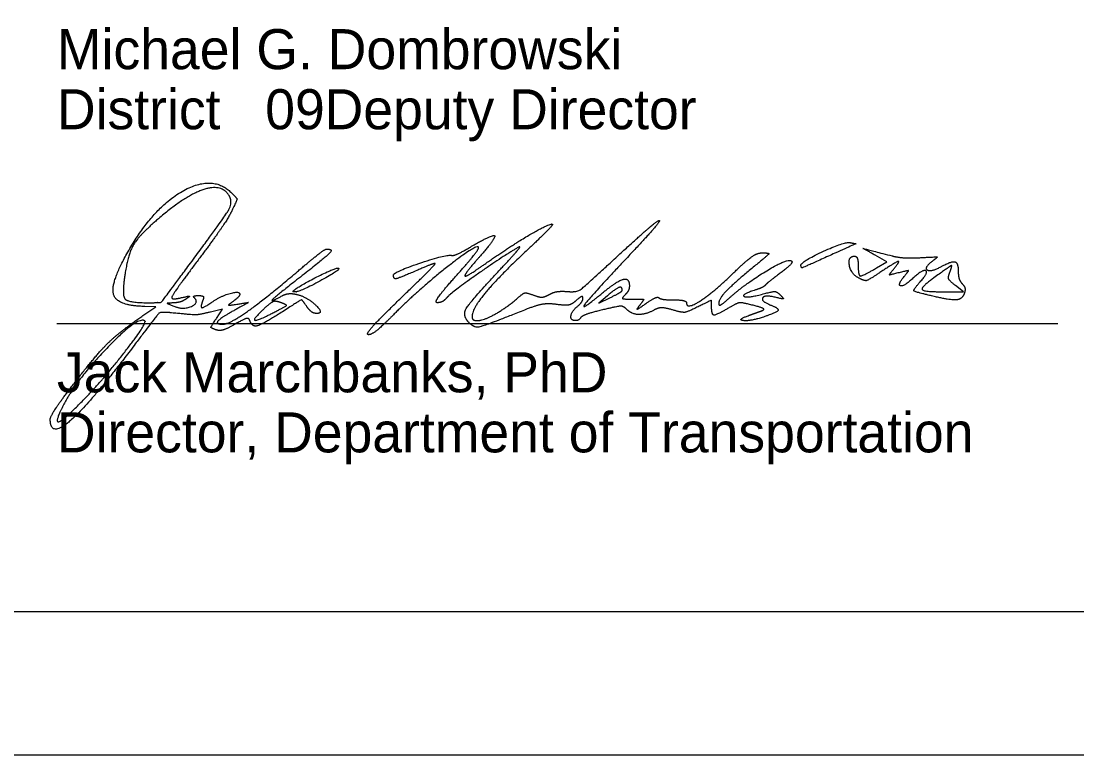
# Model space of a CAD drawing. Extents: x 0 to 34, y 0 to 22.
# Drawn here: x 27.362 to 31.053, y 0 to 2.565 of the extents above; entities that cross this region are included whole.
import ezdxf

# ---------------------------------------------------------------- set-up
doc = ezdxf.new("R2010")
doc.units = 0
for name, color, linetype in [('SH_Border', 7, 'Continuous'), ('SH_Cut_Line', 7, 'Continuous'), ('SH_Data', 7, 'Continuous'), ('SH_Text', 7, 'Continuous')]:
    doc.layers.add(name, color=color, linetype=linetype)

msp = doc.modelspace()

# ---------------------------------------------------------------- linework, layer by layer
at = {"layer": 'SH_Border'}
msp.add_lwpolyline([(1.5, 21.5), (33.5, 21.5), (33.5, 0.5), (1.5, 0.5)], close=True, dxfattribs=at)
at = {"layer": 'SH_Cut_Line'}
msp.add_lwpolyline([(0, 0), (34, 0), (34, 22), (0, 22)], close=True, dxfattribs=at)
at = {"layer": 'SH_Data'}
msp.add_line((27.4871, 1.5073), (30.9871, 1.5073), dxfattribs=at)
at = {"layer": 'SH_Text'}
for p, q in [((27.9494, 1.7123), (27.9494, 1.7123)), ((30.0887, 1.7115), (30.0887, 1.7115)), ((29.4637, 1.6245), (29.4637, 1.6245)), ((28.3147, 1.6225), (28.3147, 1.6225)), ((28.6865, 1.5934), (28.6865, 1.5934)), ((30.5412, 1.6052), (30.5412, 1.6052)), ((28.2699, 1.5808), (28.2699, 1.5808))]:
    msp.add_line(p, q, dxfattribs=at)
for points in [[(30.3525, 1.7019), (30.3889, 1.7234), (30.3481, 1.7464)], [(30.6012, 1.6184), (30.6574, 1.6185), (30.6287, 1.6406)], [(29.4119, 1.6048), (29.3824, 1.5792), (29.423, 1.5989)], [(27.8017, 1.5454), (27.8324, 1.5666), (27.7946, 1.5673)], [(28.0447, 1.5255), (28.0659, 1.5579), (28.0241, 1.5478)]]:
    msp.add_lwpolyline(points, dxfattribs=at)
for points in [[(27.7381, 1.7631), (27.8243, 1.9135), (28.0324, 2.0295), (28.0981, 1.9638)], [(28.0891, 1.9546), (28.0632, 1.9967), (27.9371, 1.9555), (27.8417, 1.8739)], [(28.0981, 1.9638), (28.1169, 1.9451), (28.1169, 1.94), (28.0986, 1.9016)], [(27.9494, 1.7123), (28.0707, 1.8758), (28.1032, 1.932), (28.0891, 1.9546)], [(28.0986, 1.9016), (28.0876, 1.8786), (28.0359, 1.803), (27.9837, 1.7337)], [(27.8417, 1.8739), (27.7751, 1.8168), (27.7363, 1.7527), (27.7252, 1.6815)], [(28.9918, 1.7216), (29.0723, 1.7782), (29.2037, 1.8554), (29.2194, 1.8554)], [(29.2194, 1.8554), (29.2242, 1.8554), (29.1829, 1.8128), (29.1276, 1.7607)], [(29.4461, 1.742), (29.5211, 1.8111), (29.5871, 1.8677), (29.5928, 1.8678)], [(29.5928, 1.8678), (29.5986, 1.8678), (29.5465, 1.8077), (29.4772, 1.7341)], [(28.9328, 1.7751), (29.0116, 1.8212), (29.0238, 1.808), (28.9646, 1.7407)], [(28.9609, 1.7748), (28.9513, 1.7844), (28.7416, 1.6175), (28.6637, 1.5382)], [(29.1012, 1.7744), (29.0521, 1.7466), (28.8638, 1.6144), (28.8506, 1.5984)], [(28.8672, 1.7458), (28.8728, 1.744), (28.9023, 1.7572), (28.9328, 1.7751)], [(28.8831, 1.6744), (28.9294, 1.7262), (28.9644, 1.7713), (28.9609, 1.7748)], [(29.036, 1.6954), (29.0821, 1.7447), (29.1115, 1.7802), (29.1012, 1.7744)], [(30.0887, 1.7115), (30.0887, 1.7239), (30.2415, 1.7942), (30.2604, 1.7905)], [(30.2604, 1.7905), (30.2811, 1.7865), (30.2818, 1.7869), (30.1602, 1.7322)], [(27.7946, 1.5673), (27.6967, 1.5689), (27.6732, 1.6501), (27.7381, 1.7631)], [(28.3282, 1.6896), (28.3786, 1.7325), (28.4241, 1.7676), (28.4293, 1.7677)], [(28.4293, 1.7677), (28.4542, 1.7682), (28.4308, 1.7427), (28.3449, 1.6754)], [(28.6639, 1.6773), (28.6641, 1.6878), (28.8515, 1.751), (28.8672, 1.7458)], [(28.9646, 1.7407), (28.9366, 1.7089), (28.9137, 1.6792), (28.9137, 1.6747)], [(29.1276, 1.7607), (29.0279, 1.667), (28.9387, 1.5588), (28.9387, 1.5319)], [(29.2711, 1.6196), (29.3045, 1.6168), (29.328, 1.6332), (29.4461, 1.742)], [(29.8543, 1.6857), (29.8995, 1.7295), (29.9366, 1.7552), (29.9543, 1.7548)], [(29.9543, 1.7548), (29.9786, 1.7544), (29.9748, 1.748), (29.9262, 1.708)], [(30.2897, 1.6674), (30.2632, 1.6815), (30.2522, 1.7429), (30.2762, 1.7429)], [(30.2762, 1.7429), (30.283, 1.7429), (30.2887, 1.7288), (30.2887, 1.7117)], [(30.3481, 1.7464), (30.3053, 1.7705), (30.3044, 1.7705), (30.4074, 1.7441)], [(30.4074, 1.7441), (30.428, 1.7388), (30.473, 1.7361), (30.5074, 1.738)], [(30.5074, 1.738), (30.5623, 1.7411), (30.5672, 1.7395), (30.5473, 1.7247)], [(27.8032, 1.5804), (27.8499, 1.5804), (27.8545, 1.5845), (27.9494, 1.7123)], [(27.9837, 1.7337), (27.9314, 1.6643), (27.8887, 1.6037), (27.8887, 1.5989)], [(28.3147, 1.6225), (28.3351, 1.6403), (28.4671, 1.7061), (28.4723, 1.701)], [(28.4723, 1.701), (28.4785, 1.6948), (28.3359, 1.6179), (28.3182, 1.6179)], [(28.6865, 1.5934), (28.7575, 1.6619), (28.8129, 1.7179), (28.8094, 1.7179)], [(28.8094, 1.7179), (28.806, 1.7179), (28.777, 1.7067), (28.7449, 1.6929)], [(28.9137, 1.6747), (28.9137, 1.6703), (28.9488, 1.6914), (28.9918, 1.7216)], [(29.4772, 1.7341), (29.3477, 1.5965), (29.3156, 1.5493), (29.3978, 1.617)], [(29.9262, 1.708), (29.8521, 1.647), (29.8012, 1.5935), (29.8012, 1.5767)], [(29.8355, 1.5945), (29.8892, 1.6433), (30.0361, 1.7333), (30.053, 1.7277)], [(30.053, 1.7277), (30.0614, 1.7249), (30.0462, 1.7062), (30.0191, 1.686)], [(30.1602, 1.7322), (30.0977, 1.7041), (30.0887, 1.7015), (30.0887, 1.7115)], [(30.2887, 1.7117), (30.2887, 1.6748), (30.3029, 1.6727), (30.3525, 1.7019)], [(30.4121, 1.6971), (30.4365, 1.7267), (30.4207, 1.7229), (30.3644, 1.6857)], [(30.5473, 1.7247), (30.5185, 1.7032), (30.5414, 1.6868), (30.5751, 1.7048)], [(30.6089, 1.6861), (30.6188, 1.7119), (30.6106, 1.7088), (30.548, 1.6632)], [(30.5751, 1.7048), (30.6153, 1.7264), (30.6387, 1.7206), (30.6387, 1.6892)], [(27.7252, 1.6815), (27.7137, 1.6081), (27.7352, 1.5804), (27.8032, 1.5804)], [(28.0668, 1.5054), (28.0899, 1.5054), (28.2159, 1.5942), (28.3282, 1.6896)], [(28.3449, 1.6754), (28.2517, 1.6024), (28.2302, 1.5808), (28.2741, 1.6043)], [(28.7449, 1.6929), (28.6823, 1.6661), (28.6636, 1.6625), (28.6639, 1.6773)], [(28.8173, 1.5804), (28.807, 1.5804), (28.8359, 1.6217), (28.8831, 1.6744)], [(28.9289, 1.5098), (28.9037, 1.535), (28.9326, 1.5851), (29.036, 1.6954)], [(29.3978, 1.617), (29.4462, 1.6569), (29.4887, 1.6673), (29.4887, 1.6392)], [(29.6887, 1.5789), (29.6887, 1.5561), (29.784, 1.6175), (29.8543, 1.6857)], [(30.0191, 1.686), (29.992, 1.6658), (29.9671, 1.6458), (29.9637, 1.6415)], [(30.3644, 1.6857), (30.3244, 1.6592), (30.3111, 1.6559), (30.2897, 1.6674)], [(30.4315, 1.6854), (30.3984, 1.6771), (30.3966, 1.6782), (30.4121, 1.6971)], [(30.4516, 1.6746), (30.4662, 1.6922), (30.4639, 1.6934), (30.4315, 1.6854)], [(30.4803, 1.6659), (30.4484, 1.6359), (30.4253, 1.643), (30.4516, 1.6746)], [(30.5054, 1.6532), (30.5359, 1.6869), (30.5143, 1.6978), (30.4803, 1.6659)], [(30.548, 1.6632), (30.5053, 1.6321), (30.5218, 1.6183), (30.6012, 1.6184)], [(30.6287, 1.6406), (30.6083, 1.6563), (30.6026, 1.6695), (30.6089, 1.6861)], [(30.6387, 1.6892), (30.6387, 1.6733), (30.645, 1.654), (30.6528, 1.6462)], [(29.4637, 1.6245), (29.4637, 1.638), (29.4396, 1.6288), (29.4119, 1.6048)], [(29.423, 1.5989), (29.4454, 1.6097), (29.4637, 1.6212), (29.4637, 1.6245)], [(29.4887, 1.6392), (29.4887, 1.6302), (29.4819, 1.6162), (29.4737, 1.6079)], [(29.9293, 1.625), (29.8798, 1.6095), (29.8993, 1.5959), (29.9511, 1.6097)], [(29.9637, 1.6415), (29.9602, 1.6373), (29.9448, 1.6298), (29.9293, 1.625)], [(30.5412, 1.6052), (30.4864, 1.6182), (30.4807, 1.6259), (30.5054, 1.6532)], [(30.6528, 1.6462), (30.6606, 1.6385), (30.6636, 1.6233), (30.6595, 1.6125)], [(27.8887, 1.5989), (27.8887, 1.5941), (27.9041, 1.5938), (27.923, 1.5982)], [(27.9387, 1.5935), (27.9284, 1.5865), (27.9087, 1.5803), (27.8949, 1.5798)], [(27.8991, 1.5671), (27.929, 1.5552), (27.9852, 1.5797), (27.9678, 1.5972)], [(27.923, 1.5982), (27.9485, 1.6041), (27.9526, 1.6029), (27.9387, 1.5935)], [(27.9678, 1.5972), (27.9632, 1.6017), (27.9695, 1.6054), (27.9817, 1.6054)], [(27.9817, 1.6054), (27.9962, 1.6054), (28.0014, 1.599), (27.9966, 1.5867)], [(28.0328, 1.5848), (28.0617, 1.6046), (28.1262, 1.6221), (28.1262, 1.6101)], [(28.1262, 1.6101), (28.1262, 1.6056), (28.1164, 1.5948), (28.1045, 1.5861)], [(28.2741, 1.6043), (28.2868, 1.6111), (28.3107, 1.6132), (28.3273, 1.609)], [(28.3603, 1.5676), (28.3434, 1.5916), (28.3414, 1.5912), (28.2756, 1.5488)], [(28.3182, 1.6179), (28.3134, 1.6179), (28.3118, 1.62), (28.3147, 1.6225)], [(28.3273, 1.609), (28.3634, 1.5998), (28.4217, 1.5429), (28.395, 1.5429)], [(28.5762, 1.4686), (28.5659, 1.4688), (28.6155, 1.525), (28.6865, 1.5934)], [(28.8506, 1.5984), (28.8423, 1.5885), (28.8274, 1.5804), (28.8173, 1.5804)], [(28.9567, 1.5179), (28.9784, 1.5179), (29.0598, 1.5631), (29.0962, 1.5954)], [(29.0962, 1.5954), (29.1165, 1.6134), (29.1293, 1.6161), (29.1531, 1.6071)], [(29.1531, 1.6071), (29.1733, 1.5994), (29.1921, 1.6001), (29.2081, 1.6091)], [(29.2081, 1.6091), (29.2215, 1.6167), (29.2498, 1.6214), (29.2711, 1.6196)], [(29.3036, 1.5889), (29.2879, 1.5747), (29.2667, 1.5703), (29.2341, 1.5744)], [(29.3262, 1.5964), (29.3262, 1.6035), (29.316, 1.6001), (29.3036, 1.5889)], [(29.3074, 1.5679), (29.3177, 1.5765), (29.3262, 1.5893), (29.3262, 1.5964)], [(29.4737, 1.6079), (29.462, 1.5962), (29.4679, 1.5929), (29.5002, 1.5929)], [(29.5002, 1.5929), (29.5377, 1.5929), (29.5401, 1.5909), (29.5246, 1.5715)], [(29.5463, 1.5774), (29.5677, 1.5924), (29.5885, 1.6015), (29.5924, 1.5975)], [(29.5924, 1.5975), (29.5963, 1.5936), (29.6196, 1.5904), (29.6441, 1.5904)], [(29.6441, 1.5904), (29.6686, 1.5904), (29.6887, 1.5852), (29.6887, 1.5789)], [(29.7762, 1.5663), (29.7762, 1.5892), (29.7751, 1.5892), (29.729, 1.5664)], [(29.8012, 1.5767), (29.8012, 1.5693), (29.8166, 1.5773), (29.8355, 1.5945)], [(29.9511, 1.6097), (29.9894, 1.6199), (30.0047, 1.6193), (30.0167, 1.6071)], [(29.998, 1.5996), (29.9613, 1.6087), (29.9481, 1.5856), (29.9824, 1.5724)], [(30.0167, 1.6071), (30.0294, 1.5942), (30.0258, 1.5928), (29.998, 1.5996)], [(30.6595, 1.6125), (30.6514, 1.5914), (30.6102, 1.5889), (30.5412, 1.6052)], [(27.8949, 1.5798), (27.8725, 1.5789), (27.8729, 1.5776), (27.8991, 1.5671)], [(27.9966, 1.5867), (27.9877, 1.5634), (28.0006, 1.5627), (28.0328, 1.5848)], [(28.1114, 1.5561), (28.0603, 1.5279), (28.0405, 1.5054), (28.0668, 1.5054)], [(28.1045, 1.5861), (28.0856, 1.5723), (28.0876, 1.571), (28.1202, 1.5759)], [(28.1202, 1.5759), (28.1569, 1.5815), (28.1568, 1.5812), (28.1114, 1.5561)], [(28.2168, 1.5643), (28.1725, 1.5238), (28.1838, 1.5149), (28.2418, 1.5445)], [(28.2699, 1.5808), (28.2527, 1.5872), (28.2362, 1.582), (28.2168, 1.5643)], [(28.2418, 1.5445), (28.2882, 1.5682), (28.2917, 1.5728), (28.2699, 1.5808)], [(28.395, 1.5429), (28.3854, 1.5429), (28.3698, 1.554), (28.3603, 1.5676)], [(29.1285, 1.5573), (28.9825, 1.4996), (28.9474, 1.4913), (28.9289, 1.5098)], [(29.2341, 1.5744), (29.2049, 1.5782), (29.165, 1.5717), (29.1285, 1.5573)], [(29.3004, 1.5179), (29.2821, 1.5179), (29.2866, 1.5507), (29.3074, 1.5679)], [(29.3947, 1.5554), (29.3564, 1.5462), (29.3221, 1.534), (29.3186, 1.5283)], [(29.4791, 1.5575), (29.468, 1.5686), (29.4479, 1.5681), (29.3947, 1.5554)], [(29.5754, 1.555), (29.5446, 1.5385), (29.4968, 1.5398), (29.4791, 1.5575)], [(29.5246, 1.5715), (29.5125, 1.5565), (29.519, 1.5583), (29.5463, 1.5774)], [(29.6399, 1.5551), (29.613, 1.5628), (29.5899, 1.5627), (29.5754, 1.555)], [(29.729, 1.5664), (29.6916, 1.5479), (29.673, 1.5456), (29.6399, 1.5551)], [(29.8381, 1.5633), (29.7931, 1.5367), (29.7762, 1.5375), (29.7762, 1.5663)], [(29.9213, 1.5713), (29.8825, 1.5812), (29.8657, 1.5796), (29.8381, 1.5633)], [(29.9074, 1.5364), (29.9212, 1.5413), (29.9409, 1.5484), (29.9512, 1.5521)], [(29.9512, 1.5521), (29.9626, 1.5563), (29.9509, 1.5638), (29.9213, 1.5713)], [(29.9824, 1.5724), (30.013, 1.5607), (30.004, 1.5458), (29.9573, 1.5304)], [(27.7946, 1.5161), (27.7737, 1.5371), (27.5552, 1.3114), (27.5089, 1.221)], [(27.5508, 1.3032), (27.6284, 1.4036), (27.7085, 1.4809), (27.8017, 1.5454)], [(27.579, 1.2398), (27.6466, 1.3088), (27.8023, 1.5085), (27.7946, 1.5161)], [(27.8829, 1.5455), (27.8495, 1.5488), (27.8378, 1.5383), (27.7611, 1.4367)], [(28.0241, 1.5478), (27.9838, 1.538), (27.9615, 1.5377), (27.8829, 1.5455)], [(28.0435, 1.4855), (28.0253, 1.4925), (28.0254, 1.4961), (28.0447, 1.5255)], [(28.1612, 1.5191), (28.1583, 1.5276), (28.1391, 1.5225), (28.11, 1.5053)], [(28.2756, 1.5488), (28.2068, 1.5045), (28.1693, 1.4947), (28.1612, 1.5191)], [(28.6637, 1.5382), (28.6259, 1.4997), (28.5865, 1.4684), (28.5762, 1.4686)], [(28.9387, 1.5319), (28.9387, 1.5242), (28.9468, 1.5179), (28.9567, 1.5179)], [(29.3186, 1.5283), (29.3151, 1.5226), (29.3069, 1.5179), (29.3004, 1.5179)], [(29.9573, 1.5304), (29.9107, 1.515), (29.8634, 1.5207), (29.9074, 1.5364)], [(28.11, 1.5053), (28.0844, 1.4902), (28.0545, 1.4813), (28.0435, 1.4855)], [(27.7611, 1.4367), (27.6088, 1.2346), (27.4637, 1.1059), (27.4637, 1.1729)], [(27.4637, 1.1729), (27.4637, 1.1826), (27.5029, 1.2412), (27.5508, 1.3032)], [(27.5089, 1.221), (27.4776, 1.1601), (27.5092, 1.1685), (27.579, 1.2398)]]:
    msp.add_open_spline(points, degree=2, dxfattribs=at)

# ---------------------------------------------------------------- texts
for s, p in [('Michael G. Dombrowski', (27.4871, 2.3967)), ('District       Deputy Director', (27.4871, 2.1867)), ('              09', (27.4871, 2.1867)), ('Jack Marchbanks, PhD', (27.4871, 1.2673)), ('Director, Department of Transportation', (27.4871, 1.0573))]:
    msp.add_text(s, height=0.14, dxfattribs=at).set_placement(p)

doc.saveas('drawing.dxf')
